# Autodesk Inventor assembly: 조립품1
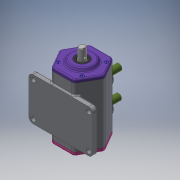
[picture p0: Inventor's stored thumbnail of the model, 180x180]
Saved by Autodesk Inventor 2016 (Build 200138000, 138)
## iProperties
Created: 2021-06
Part Number: 조립품1
Material: 일반
Document SubType Name: Assembly
Designer: pc-04
Author: pc-04
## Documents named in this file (11)
- C:\Users\pc-04\Desktop\710606V1038\조립품1.iam
- C:\Users\pc-04\Desktop\710606V1038\본체.ipt
- C:\Users\pc-04\Desktop\710606V1038\편심축.ipt
- C:\Users\pc-04\Desktop\710606V1038\베어링 6203.ipt
- C:\Users\pc-04\Desktop\710606V1038\베어링 6302.ipt
- C:\Users\pc-04\Desktop\710606V1038\슬라이더.ipt
- C:\Users\pc-04\Desktop\710606V1038\뒷커버.ipt
- C:\Users\pc-04\Desktop\710606V1038\앞커버.ipt
- C:\Users\pc-04\Desktop\710606V1038\오일실.ipt
- C:\Users\pc-04\Desktop\710606V1038\볼트 M4.ipt
- C:\Users\pc-04\Desktop\710606V1038\부시.ipt
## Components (10 placed, 3 different names)
1. 7-베어링 6203:1
2. 8-오일실:1
3. 9-M4-소켓머리:6
4. 9-M4-소켓머리:8
5. 9-M4-소켓머리:9
6. 9-M4-소켓머리:10
7. 9-M4-소켓머리:7
8. 9-M4-소켓머리:11
9. 9-M4-소켓머리:12
10. 9-M4-소켓머리:13
